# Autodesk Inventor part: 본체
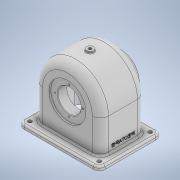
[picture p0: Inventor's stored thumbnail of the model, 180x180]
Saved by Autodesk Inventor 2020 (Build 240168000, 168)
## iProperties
Created: 2022-09
Part Number: 본체
Material: 일반
Document SubType Name: Modeling
Designer: Administrator
Density: 1 g/cm^3
Appearance: 기본값
Mass: 290.791 g
Surface Area: 1040.61 cm^2
Volume: 290.791 cm^3
Author: Administrator
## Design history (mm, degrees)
sketch "스케치2" dims "d2" = 114
  geometry: L1 (-57, 32)-(57, 32); L2 (57, 32)-(57, -32); L3 (57, -32)-(-57, -32); L4 (-57, -32)-(-57, 32); L5 (-57, 32)-(57, -32); L6 (57, 32)-(-57, -32); 3 further points
  constraints: 12 end point, 3 midpoint, 2 parallel, 1 horizontal, 1 perpendicular, 3 other
  dimensions: "d3" = 64 distance between parallel lines of L3 L1
extrude "돌출1" new body sketch "스케치2" stored distance "d4" = 78; taper "d5" = 0 deg
feature "쉘1" dims "d17" = 5
sketch "스케치5"
  geometry: L1 (114, -78)-(114, 0) reference; L2 (0, 0)-(114, 0) reference; L3 (0, -78)-(0, 0) reference; L4 (114, -78)-(0, -78) reference; L5 (117, 15)-(-3, 15); L6 (-13, 5)-(-13, -83); L7 (-3, -93)-(117, -93); L8 (127, -83)-(127, 5); L9 (127, 15)-(-13, -93); L10 (-13, 15)-(127, -93); C1 r 3.3 at (117, 5); C2 r 3.3 at (117, -83); C3 r 3.3 at (-3, -83); C4 r 3.3 at (-3, 5); A1 r 10 centre (117, 5) between (127, 5) and (117, 15); A2 r 10 centre (117, -83) between (117, -93) and (127, -83); A3 r 10 centre (-3, -83) between (-13, -83) and (-3, -93); A4 r 10 centre (-3, 5) between (-3, 15) and (-13, 5); 1 further point
  constraints: 12 end point, 8 centre point, 8 point on circle, 8 point on line, 8 tangent, 3 equal radius, 2 midpoint, 2 parallel, 1 coincident, 1 horizontal, 1 perpendicular
  dimensions: "d18" = 140 distance of L9.start L10.start; "d19" = 108 distance of L10.end L9.start; "d20" = 10 radius of A1; "d21" = 6.6 diameter of C1; "d22" = 6.6 diameter of C2; "d23" = 6.6 diameter of C3; "d24" = 6.6 diameter of C4
extrude "돌출3" join sketch "스케치5" distance "d25" = 7; taper "d26" = 0 deg
sketch "스케치6"
  geometry: L1 (32, 67.171)-(32, -65.92); L2 (-32, -47.3)-(-32, -40.7) reference; L3 (89, 39)-(32, 39) reference; L4 (32, 39)-(60, 39); L5 (60, 39)-(60, 20); L6 (60, 20)-(32, 20); L7 (32, 20)-(32, 39); L8 (70.97, 39)-(60, 20); L9 (70.97, 39)-(60, 39); L10 (84, 34)-(32, 34) reference; 3 further points
  constraints: 14 end point, 2 parallel, 1 collinear, 1 horizontal, 1 perpendicular, 1 point on line, 1 vertical
  dimensions: "d27" = 64 distance between parallel lines of L2 L1; "d28" = 56 diameter of L5.end L1; "d29" = 60 deg angle of L6 L8; "d30" = 14 distance from line of L10 L5.end
revolve "회전1" sketch "스케치6" stored, may be unused: angle "d31" = 90 deg
sketch "스케치7"
  geometry: A1 r 57 centre (0, 32) between (57, 32) and (-57, 32) reference; 2 further points
  constraints: 1 coincident
hole "구멍1" sketch "스케치7" at (0, 32) diameter "d32" = 40; stored, may be unused: countersink angle "d36" = 90 deg, drill point angle "d38" = 118 deg; dims "d33" = 11, "d34" = 64, "d35" = 3, "d37" = 13
sketch "스케치8"
  geometry: C1 r 31 at (0, 32); A1 r 57 centre (0, 32) between (57, 32) and (-57, 32) reference; 1 further point
  constraints: 1 centre point, 1 coincident
  dimensions: "d39" = 62 diameter of C1
extrude "돌출4" join sketch "스케치8" distance "d40" = 15; taper "d41" = 0 deg
sketch "스케치9"
  geometry: C1 r 31 at (0, 0) reference; 2 further points
  constraints: 1 coincident
hole "구멍2" sketch "스케치9" at (0, 0) diameter "d42" = 35; stored, may be unused: countersink angle "d46" = 90 deg, drill point angle "d48" = 118 deg; dims "d43" = 11, "d44" = 40, "d45" = 16, "d47" = 13
node "작업 평면1"
sketch "스케치10"
  geometry: C1 r 6 at (60, -54); 1 further point
  constraints: 1 centre point, 1 coincident
  dimensions: "d50" = 12 diameter of C1
extrude "돌출5" join sketch "스케치10" stored distance "d51" = 15; taper "d52" = 0 deg
sketch "스케치11"
  geometry: C1 r 6 at (0, 0) reference; 2 further points
  constraints: 1 coincident
hole "구멍3" sketch "스케치11" at (0, 0) diameter "d53" = 5.1881; stored, may be unused: countersink angle "d57" = 90 deg, drill point angle "d59" = 118 deg; dims "d54" = 53.5, "d55" = 40, "d56" = 16, "d58" = 16
fillet "모깎기1" dims "d60" = 14, "d61" = 9, "d62" = 0.6
sketch "스케치12"
  geometry: C1 r 31 at (0, 0) reference; A1 r 24 centre (0, 0) between (0, 24) and (24, 0); 3 further points
  constraints: 4 point on circle, 1 centre point, 1 coincident
  dimensions: "d63" = 48 diameter of A1
hole "구멍4" sketch "스케치12" at (0, 24), (24, 0), (0, -24), (-24, 0) diameter "d64" = 2.459; stored, may be unused: countersink angle "d68" = 90 deg, drill point angle "d70" = 118 deg; dims "d65" = 7, "d66" = 40, "d67" = 16, "d69" = 9
fillet "모깎기2" dims "d71" = 3, "d90" = 1
chamfer "모따기1" distance "d72" = 1; stored, may be unused: second distance "d73" = 2, angle "d74" = 45 deg
chamfer "모따기2" distance "d75" = 1; stored, may be unused: second distance "d76" = 2, angle "d77" = 45 deg
sketch "스케치13"
  geometry: C1 r 1.23 at (0, -24) reference; A1 r 24 centre (0, 0) between (24, 0) and (-24, 0); 3 further points
  constraints: 4 point on circle, 1 centre point, 1 coincident
  dimensions: "d79" = 48 diameter of A1
hole "구멍5" sketch "스케치13" at (24, 0), (-24, 0), (0, 24), (0, -24) diameter "d80" = 2.459; stored, may be unused: countersink angle "d84" = 90 deg, drill point angle "d86" = 118 deg; dims "d81" = 7, "d82" = 40, "d83" = 16, "d85" = 9
sketch "스케치14"
  geometry: L1 (5.498, -36.006)-(44.502, -36.006); L2 (44.502, -36.006)-(44.502, -57.994); L3 (44.502, -57.994)-(5.498, -57.994); L4 (5.498, -57.994)-(5.498, -36.006); L5 (69, -64)-(-19, -64) reference; 3 further points
  constraints: 2 other
  dimensions: "d87" = 17 distance from line of point (25, -47) L5
feature "엠보싱1" sketch "스케치14" dims "d18" = 140, "d19" = 108, "d20" = 10, "d21" = 6.6, "d88" = 0.5, "d89" = 0
node "솔리드1"
feature "A9D066F2-1C7D-4E18-AEED-F7BC21143FA4" dims "d80" = 2.459, "d81" = 7, "d82" = 40, "d83" = 16, "d84" = 90 deg, "d85" = 9, "d86" = 118 deg
other parameters: "d49" = -124
